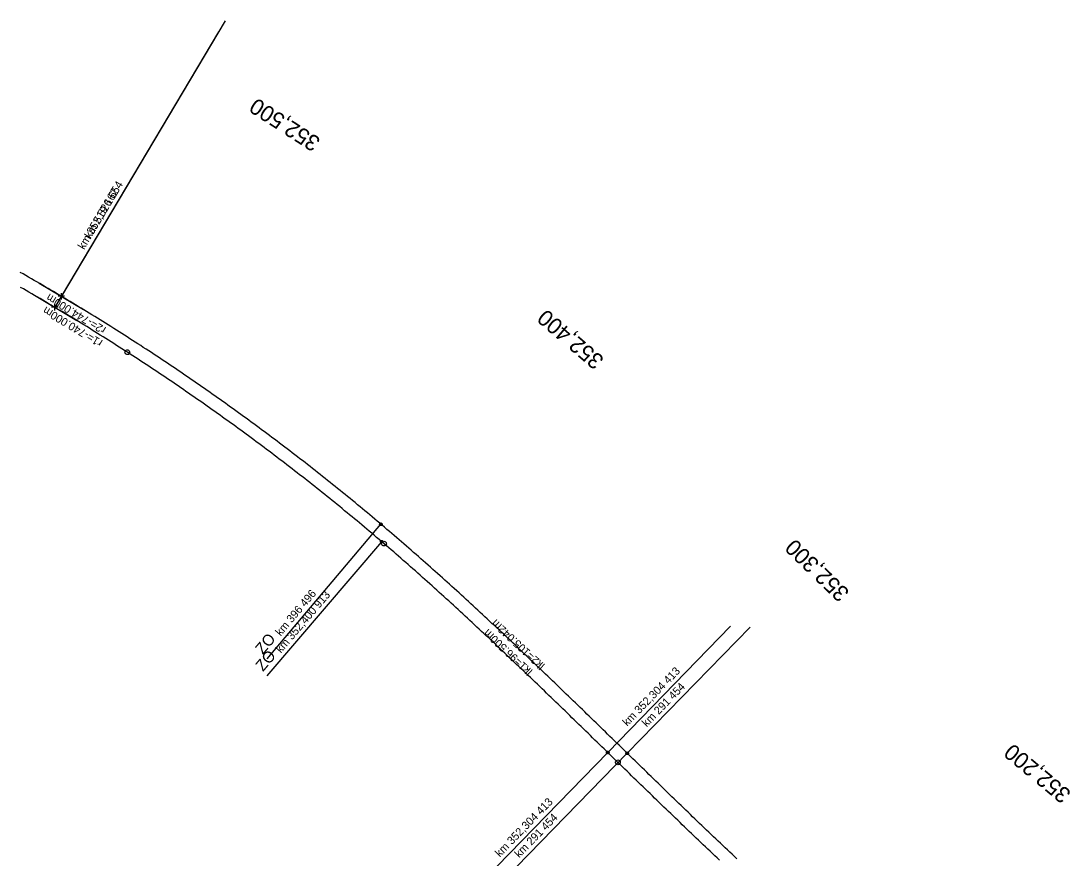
# Model space of a CAD drawing. Extents: x -825429 to 825387, y -1070027 to 1069917.
# Drawn here: x -824919.2 to -824591.7, y -1069778.7 to -1069517.4 of the extents above; entities that cross this region are included whole.
import ezdxf

# ---------------------------------------------------------------- set-up
doc = ezdxf.new("R2010")
doc.units = 0
doc.layers.add('NEW KOLEJE PALKOBAR', color=7, linetype='Continuous')
doc.layers.add('NEW KOLEJE VLADO PROVI', color=7, linetype='Continuous')

msp = doc.modelspace()

# ---------------------------------------------------------------- linework, layer by layer
at = {"layer": 'NEW KOLEJE PALKOBAR'}
for points in [[(-824695.76, -1069778.88), (-824696.49, -1069778.2), (-824697.21, -1069777.51), (-824697.94, -1069776.83), (-824698.67, -1069776.14), (-824699.39, -1069775.45), (-824700.12, -1069774.76), (-824700.85, -1069774.08), (-824701.57, -1069773.39), (-824702.29, -1069772.7), (-824703.02, -1069772.01), (-824703.74, -1069771.32), (-824704.47, -1069770.63), (-824705.19, -1069769.94), (-824705.91, -1069769.25), (-824706.63, -1069768.55), (-824707.36, -1069767.86), (-824708.08, -1069767.17), (-824708.8, -1069766.48), (-824709.52, -1069765.78), (-824710.24, -1069765.09), (-824710.96, -1069764.4), (-824711.68, -1069763.7), (-824712.4, -1069763.01), (-824713.12, -1069762.31), (-824713.84, -1069761.62), (-824714.56, -1069760.92), (-824715.28, -1069760.23), (-824715.99, -1069759.53), (-824716.71, -1069758.84), (-824717.43, -1069758.14), (-824718.15, -1069757.44), (-824718.87, -1069756.75), (-824719.58, -1069756.05), (-824720.3, -1069755.35), (-824721.02, -1069754.66), (-824721.73, -1069753.96), (-824722.45, -1069753.26), (-824723.17, -1069752.57), (-824723.88, -1069751.87), (-824724.6, -1069751.17), (-824725.32, -1069750.47), (-824726.03, -1069749.78), (-824726.75, -1069749.08), (-824727.47, -1069748.38), (-824728.18, -1069747.68), (-824728.9, -1069746.98), (-824729.61, -1069746.29), (-824729.94, -1069745.97), (-824730.33, -1069745.59), (-824731.05, -1069744.89), (-824731.76, -1069744.19), (-824732.48, -1069743.49), (-824733.2, -1069742.8), (-824733.91, -1069742.1), (-824734.63, -1069741.4), (-824735.35, -1069740.7), (-824736.06, -1069740.01), (-824736.78, -1069739.31), (-824737.49, -1069738.61), (-824738.21, -1069737.91), (-824738.93, -1069737.22), (-824739.65, -1069736.52), (-824740.36, -1069735.82), (-824741.08, -1069735.13), (-824741.8, -1069734.43), (-824742.51, -1069733.73), (-824743.23, -1069733.04), (-824743.95, -1069732.34), (-824744.67, -1069731.64), (-824745.39, -1069730.95), (-824746.1, -1069730.25), (-824746.82, -1069729.56), (-824747.54, -1069728.86), (-824748.26, -1069728.17), (-824748.98, -1069727.47), (-824749.7, -1069726.78), (-824750.42, -1069726.08), (-824751.14, -1069725.39), (-824751.86, -1069724.69), (-824752.58, -1069724), (-824753.3, -1069723.31), (-824754.02, -1069722.62), (-824754.74, -1069721.92), (-824755.47, -1069721.23), (-824756.19, -1069720.54), (-824756.91, -1069719.85), (-824757.63, -1069719.16), (-824758.35, -1069718.47), (-824759.08, -1069717.77), (-824759.8, -1069717.08), (-824760.53, -1069716.39), (-824761.25, -1069715.71), (-824761.98, -1069715.02), (-824762.7, -1069714.33), (-824763.43, -1069713.64), (-824764.15, -1069712.95), (-824764.88, -1069712.26), (-824765.61, -1069711.58), (-824766.33, -1069710.89), (-824767.06, -1069710.21), (-824767.79, -1069709.52), (-824768.52, -1069708.84), (-824769.25, -1069708.15), (-824769.98, -1069707.47), (-824770.71, -1069706.78), (-824771.44, -1069706.1), (-824772.17, -1069705.42), (-824772.9, -1069704.74), (-824773.63, -1069704.06), (-824774.36, -1069703.38), (-824775.1, -1069702.7), (-824775.83, -1069702.02), (-824776.57, -1069701.34), (-824777.3, -1069700.66), (-824778.04, -1069699.98), (-824778.77, -1069699.3), (-824779.51, -1069698.63), (-824780.25, -1069697.95), (-824780.98, -1069697.28), (-824781.72, -1069696.6), (-824782.46, -1069695.93), (-824783.2, -1069695.26), (-824783.94, -1069694.58), (-824784.68, -1069693.91), (-824785.42, -1069693.24), (-824786.16, -1069692.57), (-824786.91, -1069691.9), (-824787.65, -1069691.23), (-824788.4, -1069690.56), (-824789.14, -1069689.9), (-824789.89, -1069689.23), (-824790.63, -1069688.57), (-824791.38, -1069687.9), (-824792.13, -1069687.24), (-824792.88, -1069686.57), (-824793.62, -1069685.91), (-824794.37, -1069685.25), (-824795.12, -1069684.59), (-824795.88, -1069683.93), (-824796.63, -1069683.27), (-824797.38, -1069682.61), (-824798.14, -1069681.95), (-824798.89, -1069681.3), (-824799.65, -1069680.64), (-824800.4, -1069679.99), (-824801.16, -1069679.34), (-824801.92, -1069678.68), (-824802.67, -1069678.03), (-824803.43, -1069677.38), (-824804.19, -1069676.73), (-824804.96, -1069676.08), (-824805.72, -1069675.43), (-824806.48, -1069674.79), (-824806.86, -1069674.47), (-824807.24, -1069674.14), (-824808.01, -1069673.5), (-824808.77, -1069672.85), (-824809.54, -1069672.21), (-824810.31, -1069671.57), (-824811.07, -1069670.93), (-824811.84, -1069670.29), (-824812.61, -1069669.65), (-824813.38, -1069669.01), (-824814.16, -1069668.38), (-824814.93, -1069667.74), (-824815.7, -1069667.11), (-824816.47, -1069666.48), (-824817.25, -1069665.84), (-824818.03, -1069665.21), (-824818.8, -1069664.58), (-824819.58, -1069663.95), (-824820.36, -1069663.32), (-824821.14, -1069662.7), (-824821.92, -1069662.07), (-824822.7, -1069661.45), (-824823.48, -1069660.82), (-824824.26, -1069660.2), (-824825.04, -1069659.58), (-824825.83, -1069658.96), (-824826.61, -1069658.34), (-824827.4, -1069657.72), (-824828.19, -1069657.1), (-824828.97, -1069656.49), (-824829.76, -1069655.87), (-824830.55, -1069655.26), (-824831.34, -1069654.64), (-824832.13, -1069654.03), (-824832.92, -1069653.42), (-824833.71, -1069652.81), (-824834.51, -1069652.2), (-824835.3, -1069651.59), (-824836.1, -1069650.99), (-824836.89, -1069650.38), (-824837.69, -1069649.77), (-824838.49, -1069649.17), (-824839.28, -1069648.57), (-824840.08, -1069647.97), (-824840.88, -1069647.37), (-824841.68, -1069646.77), (-824842.48, -1069646.17), (-824843.29, -1069645.57), (-824844.09, -1069644.98), (-824844.89, -1069644.38), (-824845.7, -1069643.79), (-824846.5, -1069643.19), (-824847.31, -1069642.6), (-824848.12, -1069642.01), (-824848.92, -1069641.42), (-824849.73, -1069640.83), (-824850.54, -1069640.25), (-824851.35, -1069639.66), (-824852.16, -1069639.07), (-824852.97, -1069638.49), (-824853.79, -1069637.91), (-824854.6, -1069637.32), (-824855.41, -1069636.74), (-824856.23, -1069636.16), (-824857.04, -1069635.59), (-824857.86, -1069635.01), (-824858.68, -1069634.43), (-824859.49, -1069633.86), (-824860.31, -1069633.28), (-824861.13, -1069632.71), (-824861.95, -1069632.14), (-824862.77, -1069631.56), (-824863.59, -1069630.99), (-824864.42, -1069630.43), (-824865.24, -1069629.86), (-824866.06, -1069629.29), (-824866.89, -1069628.73), (-824867.71, -1069628.16), (-824868.54, -1069627.6), (-824869.37, -1069627.04), (-824870.2, -1069626.48), (-824871.02, -1069625.92), (-824871.85, -1069625.36), (-824872.68, -1069624.8), (-824873.51, -1069624.24), (-824874.35, -1069623.69), (-824875.18, -1069623.13), (-824876.01, -1069622.58), (-824876.85, -1069622.03), (-824877.68, -1069621.48), (-824878.51, -1069620.93), (-824879.35, -1069620.38), (-824880.19, -1069619.83), (-824881.03, -1069619.28), (-824881.86, -1069618.74), (-824882.7, -1069618.19), (-824883.54, -1069617.65), (-824884.38, -1069617.11), (-824885.22, -1069616.57), (-824886.07, -1069616.03), (-824886.91, -1069615.49), (-824887.75, -1069614.95), (-824888.59, -1069614.42), (-824889.44, -1069613.88), (-824890.29, -1069613.35), (-824891.13, -1069612.81), (-824891.98, -1069612.28), (-824892.83, -1069611.75), (-824893.67, -1069611.22), (-824894.52, -1069610.69), (-824895.37, -1069610.17), (-824896.22, -1069609.64), (-824897.07, -1069609.11), (-824897.93, -1069608.59), (-824898.78, -1069608.07), (-824899.63, -1069607.55), (-824900.49, -1069607.03), (-824901.34, -1069606.51), (-824902.2, -1069605.99), (-824903.05, -1069605.47), (-824903.91, -1069604.96), (-824904.77, -1069604.44), (-824905.62, -1069603.93), (-824906.06, -1069603.67), (-824906.48, -1069603.42), (-824906.62, -1069603.33), (-824907.18, -1069603), (-824907.34, -1069602.9), (-824908.2, -1069602.39), (-824909.06, -1069601.89), (-824909.92, -1069601.38), (-824910.79, -1069600.87), (-824911.65, -1069600.37), (-824912.51, -1069599.86), (-824913.38, -1069599.36), (-824914.24, -1069598.86), (-824915.11, -1069598.36), (-824915.97, -1069597.86), (-824916.84, -1069597.36), (-824917.71, -1069596.86), (-824918.58, -1069596.37), (-824919.45, -1069595.87)], [(-824701.16, -1069779.32), (-824701.89, -1069778.63), (-824702.62, -1069777.94), (-824703.34, -1069777.26), (-824704.07, -1069776.57), (-824704.79, -1069775.88), (-824705.52, -1069775.19), (-824706.24, -1069774.5), (-824706.97, -1069773.81), (-824707.69, -1069773.12), (-824708.42, -1069772.43), (-824709.14, -1069771.74), (-824709.86, -1069771.05), (-824710.59, -1069770.36), (-824711.31, -1069769.67), (-824712.03, -1069768.98), (-824712.75, -1069768.29), (-824713.47, -1069767.59), (-824714.19, -1069766.9), (-824714.91, -1069766.21), (-824715.64, -1069765.51), (-824716.36, -1069764.82), (-824717.08, -1069764.13), (-824717.79, -1069763.43), (-824718.51, -1069762.74), (-824719.23, -1069762.04), (-824719.95, -1069761.35), (-824720.67, -1069760.65), (-824721.39, -1069759.96), (-824722.11, -1069759.26), (-824722.83, -1069758.56), (-824723.54, -1069757.87), (-824724.26, -1069757.17), (-824724.98, -1069756.48), (-824725.7, -1069755.78), (-824726.41, -1069755.08), (-824727.13, -1069754.39), (-824727.85, -1069753.69), (-824728.57, -1069752.99), (-824729.28, -1069752.29), (-824730, -1069751.6), (-824730.72, -1069750.9), (-824731.43, -1069750.2), (-824732.15, -1069749.51), (-824732.87, -1069748.81), (-824733.58, -1069748.11), (-824734.3, -1069747.41), (-824735.02, -1069746.71), (-824735.73, -1069746.02), (-824736.03, -1069745.73), (-824736.45, -1069745.32), (-824737.17, -1069744.62), (-824737.88, -1069743.92), (-824738.6, -1069743.23), (-824739.31, -1069742.53), (-824740.03, -1069741.83), (-824740.75, -1069741.13), (-824741.46, -1069740.44), (-824742.18, -1069739.74), (-824742.9, -1069739.04), (-824743.62, -1069738.35), (-824744.33, -1069737.65), (-824745.05, -1069736.95), (-824745.77, -1069736.25), (-824746.48, -1069735.56), (-824747.2, -1069734.86), (-824747.92, -1069734.16), (-824748.64, -1069733.47), (-824749.36, -1069732.77), (-824750.07, -1069732.08), (-824750.79, -1069731.38), (-824751.51, -1069730.69), (-824752.23, -1069729.99), (-824752.95, -1069729.3), (-824753.67, -1069728.6), (-824754.39, -1069727.91), (-824755.11, -1069727.21), (-824755.83, -1069726.52), (-824756.55, -1069725.82), (-824757.27, -1069725.13), (-824757.99, -1069724.44), (-824758.71, -1069723.75), (-824759.43, -1069723.05), (-824760.15, -1069722.36), (-824760.88, -1069721.67), (-824761.6, -1069720.98), (-824762.32, -1069720.29), (-824763.04, -1069719.6), (-824763.77, -1069718.91), (-824764.49, -1069718.22), (-824765.22, -1069717.53), (-824765.94, -1069716.84), (-824766.66, -1069716.15), (-824767.39, -1069715.46), (-824768.12, -1069714.77), (-824768.84, -1069714.08), (-824769.57, -1069713.4), (-824770.3, -1069712.71), (-824771.02, -1069712.03), (-824771.75, -1069711.34), (-824772.48, -1069710.66), (-824773.21, -1069709.97), (-824773.94, -1069709.29), (-824774.67, -1069708.6), (-824775.4, -1069707.92), (-824776.13, -1069707.24), (-824776.86, -1069706.56), (-824777.59, -1069705.88), (-824778.33, -1069705.19), (-824779.06, -1069704.51), (-824779.79, -1069703.84), (-824780.53, -1069703.16), (-824781.26, -1069702.48), (-824782, -1069701.8), (-824782.74, -1069701.12), (-824783.47, -1069700.45), (-824784.21, -1069699.77), (-824784.95, -1069699.1), (-824785.69, -1069698.42), (-824786.43, -1069697.75), (-824787.17, -1069697.08), (-824787.91, -1069696.41), (-824788.65, -1069695.74), (-824789.39, -1069695.07), (-824790.13, -1069694.4), (-824790.88, -1069693.73), (-824791.62, -1069693.06), (-824792.37, -1069692.39), (-824793.11, -1069691.73), (-824793.86, -1069691.06), (-824794.6, -1069690.39), (-824795.35, -1069689.73), (-824796.1, -1069689.07), (-824796.85, -1069688.41), (-824797.6, -1069687.74), (-824798.35, -1069687.08), (-824799.1, -1069686.42), (-824799.86, -1069685.77), (-824800.61, -1069685.11), (-824801.36, -1069684.45), (-824802.12, -1069683.8), (-824802.87, -1069683.14), (-824803.63, -1069682.49), (-824804.39, -1069681.83), (-824805.15, -1069681.18), (-824805.9, -1069680.53), (-824806.6, -1069679.94), (-824806.66, -1069679.88), (-824807.43, -1069679.23), (-824808.19, -1069678.58), (-824808.95, -1069677.94), (-824809.71, -1069677.29), (-824810.48, -1069676.65), (-824811.24, -1069676), (-824812.01, -1069675.36), (-824812.78, -1069674.72), (-824813.54, -1069674.08), (-824814.31, -1069673.44), (-824815.08, -1069672.8), (-824815.85, -1069672.16), (-824816.62, -1069671.53), (-824817.4, -1069670.89), (-824818.17, -1069670.26), (-824818.94, -1069669.62), (-824819.72, -1069668.99), (-824820.49, -1069668.36), (-824821.27, -1069667.73), (-824822.05, -1069667.1), (-824822.83, -1069666.47), (-824823.6, -1069665.85), (-824824.38, -1069665.22), (-824825.17, -1069664.59), (-824825.95, -1069663.97), (-824826.73, -1069663.35), (-824827.51, -1069662.73), (-824828.3, -1069662.11), (-824829.08, -1069661.49), (-824829.87, -1069660.87), (-824830.65, -1069660.25), (-824831.44, -1069659.63), (-824832.23, -1069659.02), (-824833.02, -1069658.4), (-824833.81, -1069657.79), (-824834.6, -1069657.18), (-824835.39, -1069656.57), (-824836.18, -1069655.96), (-824836.98, -1069655.35), (-824837.77, -1069654.74), (-824838.57, -1069654.13), (-824839.36, -1069653.53), (-824840.16, -1069652.92), (-824840.95, -1069652.32), (-824841.75, -1069651.72), (-824842.55, -1069651.12), (-824843.35, -1069650.51), (-824844.15, -1069649.92), (-824844.95, -1069649.32), (-824845.76, -1069648.72), (-824846.56, -1069648.12), (-824847.36, -1069647.53), (-824848.17, -1069646.94), (-824848.97, -1069646.34), (-824849.78, -1069645.75), (-824850.59, -1069645.16), (-824851.39, -1069644.57), (-824852.2, -1069643.98), (-824853.01, -1069643.4), (-824853.82, -1069642.81), (-824854.63, -1069642.22), (-824855.44, -1069641.64), (-824856.26, -1069641.06), (-824857.07, -1069640.48), (-824857.88, -1069639.89), (-824858.7, -1069639.31), (-824859.51, -1069638.74), (-824860.33, -1069638.16), (-824861.15, -1069637.58), (-824861.97, -1069637.01), (-824862.78, -1069636.43), (-824863.6, -1069635.86), (-824864.42, -1069635.29), (-824865.25, -1069634.72), (-824866.07, -1069634.15), (-824866.89, -1069633.58), (-824867.71, -1069633.01), (-824868.54, -1069632.45), (-824869.36, -1069631.88), (-824870.19, -1069631.32), (-824871.01, -1069630.75), (-824871.84, -1069630.19), (-824872.67, -1069629.63), (-824873.5, -1069629.07), (-824874.33, -1069628.51), (-824875.16, -1069627.96), (-824875.99, -1069627.4), (-824876.82, -1069626.84), (-824877.65, -1069626.29), (-824878.49, -1069625.74), (-824879.32, -1069625.19), (-824880.16, -1069624.63), (-824880.99, -1069624.08), (-824881.83, -1069623.54), (-824882.66, -1069622.99), (-824883.5, -1069622.44), (-824884.34, -1069621.9), (-824885.18, -1069621.35), (-824886.02, -1069620.81), (-824886.86, -1069620.27), (-824887.7, -1069619.73), (-824888.54, -1069619.19), (-824889.39, -1069618.65), (-824890.23, -1069618.12), (-824891.07, -1069617.58), (-824891.92, -1069617.04), (-824892.77, -1069616.51), (-824893.61, -1069615.98), (-824894.46, -1069615.45), (-824895.31, -1069614.92), (-824896.16, -1069614.39), (-824897, -1069613.86), (-824897.85, -1069613.33), (-824898.71, -1069612.81), (-824899.56, -1069612.28), (-824900.41, -1069611.76), (-824901.26, -1069611.24), (-824902.12, -1069610.72), (-824902.97, -1069610.2), (-824903.82, -1069609.68), (-824904.68, -1069609.16), (-824905.54, -1069608.64), (-824906.39, -1069608.13), (-824907.25, -1069607.62), (-824908.11, -1069607.1), (-824908.18, -1069607.06), (-824908.67, -1069606.77), (-824908.97, -1069606.59), (-824909.16, -1069606.48), (-824909.83, -1069606.08), (-824910.69, -1069605.57), (-824911.55, -1069605.06), (-824912.41, -1069604.56), (-824913.28, -1069604.05), (-824914.14, -1069603.54), (-824915, -1069603.04), (-824915.87, -1069602.54), (-824916.73, -1069602.04), (-824917.6, -1069601.54), (-824918.47, -1069601.04), (-824919.33, -1069600.54)], [(-824886.43, -1069621.44), (-824886.61, -1069621.26), (-824886.74, -1069621), (-824886.78, -1069620.8), (-824886.73, -1069620.53), (-824886.57, -1069620.28), (-824886.38, -1069620.17), (-824886.14, -1069620.08), (-824885.85, -1069620.09), (-824885.61, -1069620.18), (-824885.43, -1069620.36), (-824885.3, -1069620.62), (-824885.26, -1069620.83), (-824885.31, -1069621.09), (-824885.47, -1069621.34), (-824885.66, -1069621.46), (-824885.9, -1069621.54), (-824886.19, -1069621.54), (-824886.43, -1069621.44)], [(-824806.39, -1069681.1), (-824806.55, -1069680.9), (-824806.64, -1069680.62), (-824806.66, -1069680.41), (-824806.57, -1069680.16), (-824806.38, -1069679.93), (-824806.17, -1069679.84), (-824805.93, -1069679.79), (-824805.64, -1069679.84), (-824805.42, -1069679.96), (-824805.26, -1069680.16), (-824805.17, -1069680.44), (-824805.15, -1069680.65), (-824805.24, -1069680.9), (-824805.43, -1069681.13), (-824805.64, -1069681.22), (-824805.88, -1069681.27), (-824806.17, -1069681.23), (-824806.39, -1069681.1)], [(-824733.39, -1069749.34), (-824733.53, -1069749.13), (-824733.61, -1069748.85), (-824733.61, -1069748.64), (-824733.51, -1069748.39), (-824733.3, -1069748.18), (-824733.09, -1069748.1), (-824732.84, -1069748.06), (-824732.56, -1069748.13), (-824732.34, -1069748.27), (-824732.2, -1069748.48), (-824732.12, -1069748.76), (-824732.12, -1069748.97), (-824732.22, -1069749.22), (-824732.43, -1069749.44), (-824732.64, -1069749.51), (-824732.89, -1069749.55), (-824733.18, -1069749.48), (-824733.39, -1069749.34)]]:
    msp.add_lwpolyline(points, dxfattribs=at)
at = {"layer": 'NEW KOLEJE VLADO PROVI'}
for p, q in [((-824906.62, -1069604.33), (-824906.62, -1069602.33)), ((-824908.67, -1069607.77), (-824908.67, -1069605.77)), ((-824905.62, -1069603.33), (-824907.62, -1069603.33)), ((-824907.67, -1069606.77), (-824909.67, -1069606.77))]:
    msp.add_line(p, q, dxfattribs=at)
for points in [[(-824855.47, -1069517.41), (-824906.62, -1069603.33)], [(-824857.52, -1069520.84), (-824908.67, -1069606.77)], [(-824913.5, -1069599.24), (-824899.75, -1069607.42)], [(-824915.55, -1069602.68), (-824901.8, -1069610.86)], [(-824842.37, -1069716.47), (-824806.86, -1069674.47)], [(-824806.6, -1069674.16), (-824806.52, -1069674.27), (-824806.47, -1069674.42), (-824806.46, -1069674.53), (-824806.5, -1069674.66), (-824806.61, -1069674.79), (-824806.71, -1069674.83), (-824806.84, -1069674.86), (-824807, -1069674.84), (-824807.12, -1069674.77), (-824807.2, -1069674.67), (-824807.25, -1069674.52), (-824807.26, -1069674.41), (-824807.22, -1069674.27), (-824807.11, -1069674.15), (-824807, -1069674.1), (-824806.87, -1069674.07), (-824806.72, -1069674.1), (-824806.6, -1069674.16)], [(-824842.32, -1069721.76), (-824806.6, -1069679.94)], [(-824806.34, -1069679.63), (-824806.25, -1069679.74), (-824806.21, -1069679.89), (-824806.2, -1069680), (-824806.24, -1069680.14), (-824806.35, -1069680.26), (-824806.46, -1069680.3), (-824806.59, -1069680.33), (-824806.74, -1069680.31), (-824806.86, -1069680.24), (-824806.94, -1069680.13), (-824806.99, -1069679.99), (-824807, -1069679.87), (-824806.95, -1069679.74), (-824806.85, -1069679.62), (-824806.74, -1069679.57), (-824806.61, -1069679.54), (-824806.46, -1069679.57), (-824806.34, -1069679.63)], [(-824736.03, -1069745.73), (-824697.66, -1069706.32)], [(-824729.94, -1069745.97), (-824691.56, -1069706.58)], [(-824774.4, -1069785.13), (-824736.03, -1069745.73)], [(-824768.32, -1069785.36), (-824729.94, -1069745.97)], [(-824736.31, -1069746.02), (-824736.38, -1069745.9), (-824736.42, -1069745.75), (-824736.43, -1069745.64), (-824736.37, -1069745.51), (-824736.26, -1069745.39), (-824736.15, -1069745.35), (-824736.01, -1069745.33), (-824735.86, -1069745.37), (-824735.75, -1069745.44), (-824735.67, -1069745.55), (-824735.63, -1069745.71), (-824735.63, -1069745.82), (-824735.69, -1069745.95), (-824735.8, -1069746.07), (-824735.91, -1069746.1), (-824736.04, -1069746.13), (-824736.19, -1069746.09), (-824736.31, -1069746.02)], [(-824730.22, -1069746.26), (-824730.3, -1069746.14), (-824730.34, -1069745.99), (-824730.34, -1069745.88), (-824730.28, -1069745.75), (-824730.17, -1069745.63), (-824730.06, -1069745.59), (-824729.93, -1069745.57), (-824729.78, -1069745.61), (-824729.66, -1069745.68), (-824729.58, -1069745.79), (-824729.54, -1069745.94), (-824729.54, -1069746.06), (-824729.6, -1069746.19), (-824729.71, -1069746.31), (-824729.82, -1069746.34), (-824729.95, -1069746.36), (-824730.11, -1069746.33), (-824730.22, -1069746.26)]]:
    msp.add_lwpolyline(points, dxfattribs=at)

# ---------------------------------------------------------------- texts
at = {"layer": 'NEW KOLEJE PALKOBAR'}
for s, rotation, p in [('352,500', 147.2598, (-824825.4, -1069554.27)), ('352,400', 139.5175, (-824736.88, -1069622.77)), ('352,300', 135.8596, (-824660.29, -1069695.56)), ('352,200', 140.1432, (-824591.05, -1069758.15))]:
    msp.add_text(s, height=5, rotation=rotation, dxfattribs=at).set_placement(p)
at = {"layer": 'NEW KOLEJE VLADO PROVI'}
for s, height, rotation, p in [('km 352,526 654', 2.5, 59.2335, (-824899.52, -1069588.94)), ('km 519 162', 2.5, 59.2332, (-824897.47, -1069585.51)), ('r2=-744.000m', 2.5, 149.0642, (-824892.45, -1069613.13)), ('r1=-740.000m', 2.5, 148.9726, (-824893.51, -1069617.19)), ('km 396 496', 2.5, 49.7867, (-824838.16, -1069709.55)), ('km 352,400 913', 2.5, 49.4978, (-824838.07, -1069714.86)), ('lk2=105.042m', 2.5, 137.0902, (-824755.46, -1069718.32)), ('lk1=96.500m', 2.5, 137.0072, (-824759.3, -1069720.11)), ('ZO', 3.5, 49.7867, (-824843.71, -1069715.34)), ('ZO', 3.5, 49.4978, (-824843.65, -1069720.62)), ('km 352,304 413', 2.5, 45.762, (-824729.95, -1069737.69)), ('km 291 454', 2.5, 45.742, (-824723.86, -1069737.93)), ('km 352,304 413', 2.5, 45.762, (-824769.71, -1069778.53)), ('km 291 454', 2.5, 45.742, (-824763.64, -1069778.76))]:
    msp.add_text(s, height=height, rotation=rotation, dxfattribs=at).set_placement(p)

doc.saveas('drawing.dxf')
